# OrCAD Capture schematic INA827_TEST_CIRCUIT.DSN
size A; title: INA827: Wide Supply Range, Rail-to-Rail Output; rev: 1.0; note: Datasheet: SBOS631B             EVM: SBOU121
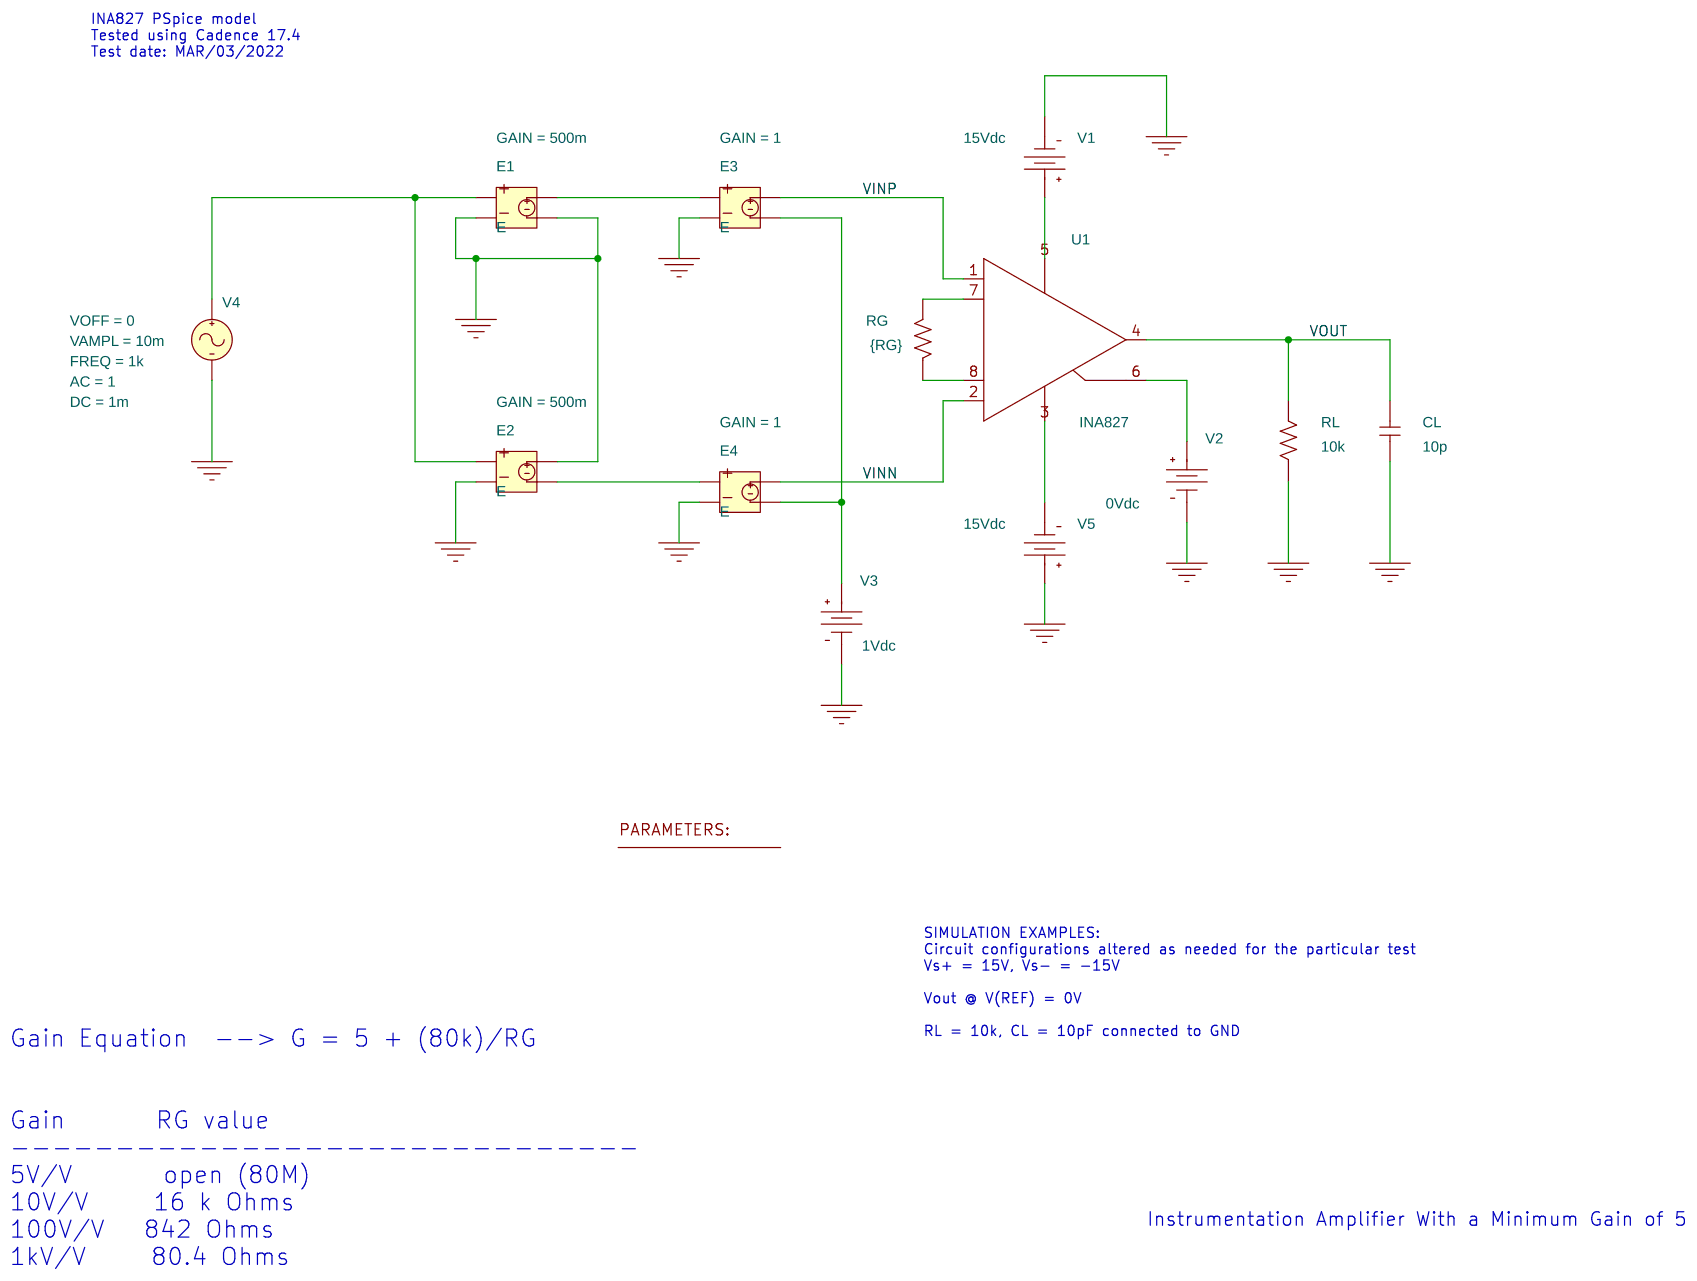
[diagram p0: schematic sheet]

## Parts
1  PARAM
CL  10p  [cap196]
E1  E
E2  E
E3  E
E4  E
RG  {RG}  [AXRC05]
RL  10k  [AXRC05]
U1  INA827
V1  VDC
V2  VDC
V3  VDC
V4  VSIN
V5  VDC

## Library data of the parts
1 = PARAM: RG: 80.4
CL = C
E1 E2 = E: GAIN: 500m
E3 E4 = E: GAIN: 1
RG RL = R
U1 = INA827
V1 V5 = VDC: DC: 15Vdc
V2 = VDC: DC: 0Vdc
V3 = VDC: DC: 1Vdc
V4 = VSIN: AC: 1; DC: 1m; FREQ: 1k; VAMPL: 10m; VOFF: 0

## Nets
VINN: E4.3 U1.2(-)
VINP: E3.3 U1.1(+)
0: CL.1 E1.2 E1.4 E2.2 E2.3 E3.2 E4.2 RL.1 V1.1(-) V2.1(-) V3.1(-) V4.2(-) V5.0(+)
VOUT: CL.2 RL.2 U1.4(OUT)
N30195: E1.1 E2.1 V4.1(+)
N30215: E1.3 E3.1
N30233: U1.5(V+) V1.0(+)
N30265: E3.4 E4.4 V3.0(+)
N30383: RG.2 U1.7(RG+)
N30475: RG.1 U1.8(RG-)
N30481: U1.6(REF) V2.0(+)
N30499: U1.3(V-) V5.1(-)
N30647: E2.4 E4.1

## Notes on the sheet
- INA827 PSpice model
  Tested using Cadence 17.4
  Test date: MAR/03/2022
- SIMULATION EXAMPLES:
  Circuit configurations altered as needed for the particular test
  Vs+ = 15V, Vs- = -15V
  Vout @ V(REF) = 0V
  RL = 10k, CL = 10pF connected to GND
- Gain Equation  --> G = 5 + (80k)/RG
  Gain       RG value
  ------------------------------
  5V/V       open (80M)
  10V/V     16 k Ohms
  100V/V   842 Ohms
  1kV/V     80.4 Ohms
- Instrumentation Amplifier With a Minimum Gain of 5
